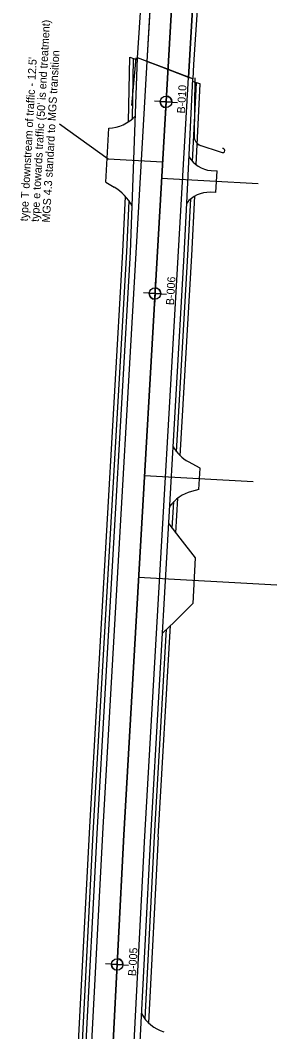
# Model space of a CAD drawing. Extents: x 1973866 to 1974130, y 734965 to 738427.
# Drawn here: x 1973970 to 1974104, y 737376 to 737903 of the extents above; entities that cross this region are included whole.
import ezdxf

# ---------------------------------------------------------------- set-up
doc = ezdxf.new("R2010")
doc.units = 0
for name, color, linetype in [('_CIVIL_CONSTRUCTION', 7, 'Continuous'), ('CM_Corridor_Range_Conceptual', 7, 'Continuous'), ('DR_P_Cells', 7, 'Continuous'), ('DR_P_Headwall', 7, 'Continuous'), ('DR_P_Storm_Sewer', 7, 'Continuous'), ('DR_X_Cells', 7, 'Continuous'), ('DR_X_GenericNode', 7, 'Continuous'), ('DR_X_Storm_Sewer', 7, 'Continuous'), ('MD_P_ACIC_B', 7, 'Continuous'), ('MD_P_AGB_T', 7, 'Continuous'), ('MD_P_Surface_Asphalt_Concrete_Base', 7, 'Continuous'), ('PF_X_Ground_Line', 7, 'Continuous'), ('PV_P_Saw_Cut_Line', 7, 'Continuous'), ('SC_Scratch1', 7, 'Continuous')]:
    doc.layers.add(name, color=color, linetype=linetype)

msp = doc.modelspace()

# ---------------------------------------------------------------- linework, layer by layer
at = {"layer": '_CIVIL_CONSTRUCTION'}
for p, q in [((1974014.85, 737818.58), (1974016.47, 737846.66)), ((1974069.75, 737824.58), (1974072.97, 737824.41)), ((1974072.33, 737813.18), (1974072.97, 737824.41)), ((1974014.85, 737818.58), (1974019.19, 737816.01)), ((1974072.33, 737813.18), (1974069.3, 737813.28)), ((1974064.16, 737669.63), (1974058.09, 737672.9)), ((1974063.47, 737658.46), (1974064.16, 737669.63)), ((1974063.47, 737658.46), (1974059.58, 737657.46)), ((1974047.67, 737640.65), (1974053.47, 737633.22)), ((1974053.47, 737633.22), (1974061.45, 737622.89)), ((1974061.45, 737622.89), (1974060.31, 737599.12)), ((1974060.31, 737599.12), (1974050.74, 737589.65)), ((1974050.74, 737589.65), (1974044.39, 737583.67))]:
    msp.add_line(p, q, dxfattribs=at)
for centre, radius, start, end in [((1974015.63, 737866.64), 20, 272.3827, 317.3244), ((1974071.14, 737839.51), 15, 210.5665, 264.6465), ((1974006.47, 737794.49), 25, 27.5139, 59.4001), ((1974068.77, 737798.29), 15, 87.9927, 141.3926), ((1974067.57, 737690.51), 20, 208.4916, 241.7135), ((1974064.55, 737638.09), 20, 104.3781, 144.9149), ((1974051.02, 737395.17), 20, 208.814, 252.6777)]:
    msp.add_arc(centre, radius, start, end, dxfattribs=at)
at = {"layer": 'CM_Corridor_Range_Conceptual'}
for p, q in [((1974026.75, 737850.02), (1974027.42, 737883.61)), ((1974027.42, 737883.61), (1974029.41, 737882.94)), ((1974062.02, 737827.61), (1974064.1, 737869.77)), ((1974064.1, 737869.77), (1974062.13, 737870.35)), ((1974023.78, 737782.38), (1974025.1, 737811.14)), ((1974059.72, 737780.37), (1974061.23, 737811.26)), ((1974006.34, 737479.65), (1974023.78, 737782.38)), ((1974053.72, 737676.08), (1974059.72, 737780.35)), ((1974051.4, 737635.87), (1974052.45, 737654.01)), ((1974042.28, 737477.58), (1974048.62, 737587.66)), ((1973992.44, 737212.09), (1974006.34, 737479.55)), ((1974037.25, 737380.67), (1974042.29, 737477.68))]:
    msp.add_line(p, q, dxfattribs=at)
at = {"layer": 'DR_P_Cells'}
for p, q in [((1974024.31, 737478.61), (1974070.59, 738282.05)), ((1974010.42, 737211.15), (1974024.31, 737478.61))]:
    msp.add_line(p, q, dxfattribs=at)
at = {"layer": 'DR_P_Headwall'}
for p, q in [((1974016.13, 737830.52), (1973990.71, 737848.73)), ((1974044.49, 737828.93), (1974016.13, 737830.52)), ((1974094.38, 737817.66), (1974044.01, 737820.48)), ((1974091.76, 737662.47), (1974035.09, 737665.65)), ((1974104.02, 737608.59), (1974032.03, 737612.62))]:
    msp.add_line(p, q, dxfattribs=at)
at = {"layer": 'DR_P_Storm_Sewer'}
for p, q in [((1974027.78, 737782.17), (1974031.43, 737883.28)), ((1974036.52, 737881.37), (1974031.43, 737883.28)), ((1974057.05, 737807.65), (1974060.2, 737872.32)), ((1974060.2, 737872.32), (1974058.06, 737873.15)), ((1974055.73, 737780.56), (1974057.05, 737807.65)), ((1974010.34, 737479.42), (1974027.78, 737782.17)), ((1974038.29, 737477.81), (1974055.73, 737780.56)), ((1973996.44, 737211.88), (1974010.33, 737479.34)), ((1974024.4, 737210.43), (1974038.29, 737477.89))]:
    msp.add_line(p, q, dxfattribs=at)
at = {"layer": 'DR_X_Cells'}
for p, q in [((1974028.78, 737851.57), (1974029.41, 737882.94)), ((1974029.41, 737882.94), (1974031.38, 737882.28)), ((1974060.11, 737829.36), (1974062.13, 737870.35)), ((1974062.13, 737870.35), (1974060.15, 737870.94)), ((1974025.78, 737782.29), (1974027, 737808.74)), ((1974057.73, 737780.47), (1974059.16, 737809.81)), ((1974008.34, 737479.53), (1974025.78, 737782.28)), ((1974051.83, 737678.17), (1974057.73, 737780.47)), ((1974049.54, 737638.26), (1974050.34, 737652.16)), ((1974040.29, 737477.69), (1974046.51, 737585.67)), ((1973994.44, 737211.98), (1974008.33, 737479.44)), ((1974035.35, 737382.74), (1974040.29, 737477.78))]:
    msp.add_line(p, q, dxfattribs=at)
at = {"layer": 'DR_X_GenericNode'}
for p, q in [((1974036.52, 737881.37), (1974042.65, 737987.79)), ((1974058.06, 737873.15), (1974064.23, 737980.24))]:
    msp.add_line(p, q, dxfattribs=at)
at = {"layer": 'DR_X_Storm_Sewer'}
for p, q in [((1974053.41, 737983.81), (1974024.31, 737478.61)), ((1974024.31, 737478.61), (1974010.42, 737211.15))]:
    msp.add_line(p, q, dxfattribs=at)
at = {"layer": 'MD_P_ACIC_B'}
for centre in [(1974046.3, 737860.39), (1974040.55, 737760.56), (1974020.81, 737411.12)]:
    msp.add_circle(centre, 0.05, dxfattribs=at)
at = {"layer": 'MD_P_Surface_Asphalt_Concrete_Base'}
for p, q in [((1974046.3, 737860.39), (1974046.64, 737866.38)), ((1974046.3, 737860.39), (1974046.47, 737863.39)), ((1974046.3, 737860.39), (1974040.31, 737860.73)), ((1974043.31, 737860.56), (1974046.3, 737860.39)), ((1974046.3, 737860.39), (1974045.97, 737854.4)), ((1974046.3, 737860.39), (1974046.14, 737857.4)), ((1974046.3, 737860.39), (1974052.3, 737860.06)), ((1974049.3, 737860.23), (1974046.3, 737860.39)), ((1974040.55, 737760.56), (1974040.89, 737766.55)), ((1974040.55, 737760.56), (1974040.72, 737763.55)), ((1974040.55, 737760.56), (1974034.56, 737760.89)), ((1974037.56, 737760.73), (1974040.55, 737760.56)), ((1974040.55, 737760.56), (1974040.22, 737754.57)), ((1974040.55, 737760.56), (1974040.39, 737757.56)), ((1974040.55, 737760.56), (1974046.54, 737760.22)), ((1974043.55, 737760.39), (1974040.55, 737760.56)), ((1974020.81, 737411.12), (1974021.14, 737417.11)), ((1974020.81, 737411.12), (1974014.82, 737411.45)), ((1974017.81, 737411.29), (1974020.81, 737411.12)), ((1974020.81, 737411.12), (1974020.47, 737405.13)), ((1974020.81, 737411.12), (1974020.64, 737408.12)), ((1974020.81, 737411.12), (1974020.97, 737414.11)), ((1974020.81, 737411.12), (1974026.8, 737410.78)), ((1974023.8, 737410.95), (1974020.81, 737411.12))]:
    msp.add_line(p, q, dxfattribs=at)
for centre in [(1974046.3, 737860.39), (1974040.55, 737760.56), (1974020.81, 737411.12)]:
    msp.add_circle(centre, 3, dxfattribs=at)
for centre, start, end in [((1974046.3, 737860.39), 356.7892, 86.7892), ((1974046.3, 737860.39), 176.7892, 266.7892), ((1974040.55, 737760.56), 356.7892, 86.7892), ((1974040.55, 737760.56), 176.7892, 266.7892), ((1974020.81, 737411.12), 176.7892, 266.7892), ((1974020.81, 737411.12), 356.7892, 86.7892)]:
    msp.add_arc(centre, 3, start, end, dxfattribs=at)
at = {"layer": 'PF_X_Ground_Line'}
for p, q in [((1974031.43, 737883.28), (1974036.22, 737955.55)), ((1974062.67, 737910.86), (1974060.68, 737879.88)), ((1974045.28, 737878.07), (1974031.43, 737883.28)), ((1974060.68, 737879.88), (1974060.2, 737872.32)), ((1974060.2, 737872.32), (1974045.28, 737878.07))]:
    msp.add_line(p, q, dxfattribs=at)
for points in [[(1974036.52, 737881.37), (1974041.1, 737960.81), (1974063.03, 737959.55), (1974058.06, 737873.15)], [(1974058.01, 737873.11), (1974045.28, 737878.02), (1974036.56, 737881.3)]]:
    msp.add_lwpolyline(points, dxfattribs=at)
for centre, start, end in [((1974036.51, 737881.32), 339.3698, 86.7002), ((1974058.05, 737873.1), 86.7032, 158.9345)]:
    msp.add_arc(centre, 0.05, start, end, dxfattribs=at)
at = {"layer": 'PV_P_Saw_Cut_Line'}
for p, q in [((1974028.53, 737858.43), (1974030.69, 737883.33)), ((1974061.36, 737872.85), (1974060.93, 737842.51)), ((1974062.87, 737838.19), (1974075.53, 737833.94))]:
    msp.add_line(p, q, dxfattribs=at)
for centre, radius, start, end in [((1974065.93, 737842.44), 5, 179.2001, 251.432), ((1974075.82, 737835.04), 1.13, 255.1757, 97.7238)]:
    msp.add_arc(centre, radius, start, end, dxfattribs=at)
at = {"layer": 'SC_Scratch1'}
for p, q in [((1974013.33, 737479.25), (1974036.52, 737881.37)), ((1974058.06, 737873.15), (1974036.52, 737881.37)), ((1974035.29, 737477.98), (1974058.06, 737873.15)), ((1973999.43, 737211.72), (1974013.33, 737479.18)), ((1974021.4, 737210.58), (1974035.3, 737478.04))]:
    msp.add_line(p, q, dxfattribs=at)

# ---------------------------------------------------------------- texts
at = {"layer": 'MD_P_AGB_T'}
for s, p in [("type e towards traffic (50' is end treatment)", (1973979.97, 737797.77)), ('MGS 4.3 standard to MGS transition', (1973985.77, 737797.44)), ("type T downstream of traffic - 12.5'", (1973974.17, 737798.09))]:
    msp.add_text(s, height=4.1667, rotation=86.7892, dxfattribs=at).set_placement(p)
at = {"layer": 'SC_Scratch1'}
for s, p in [('B-010', (1974056.14, 737854.24)), ('B-006', (1974050.39, 737754.41)), ('B-005', (1974030.64, 737404.97))]:
    msp.add_text(s, height=4.167, rotation=86.7892, dxfattribs=at).set_placement(p)

doc.saveas('drawing.dxf')
